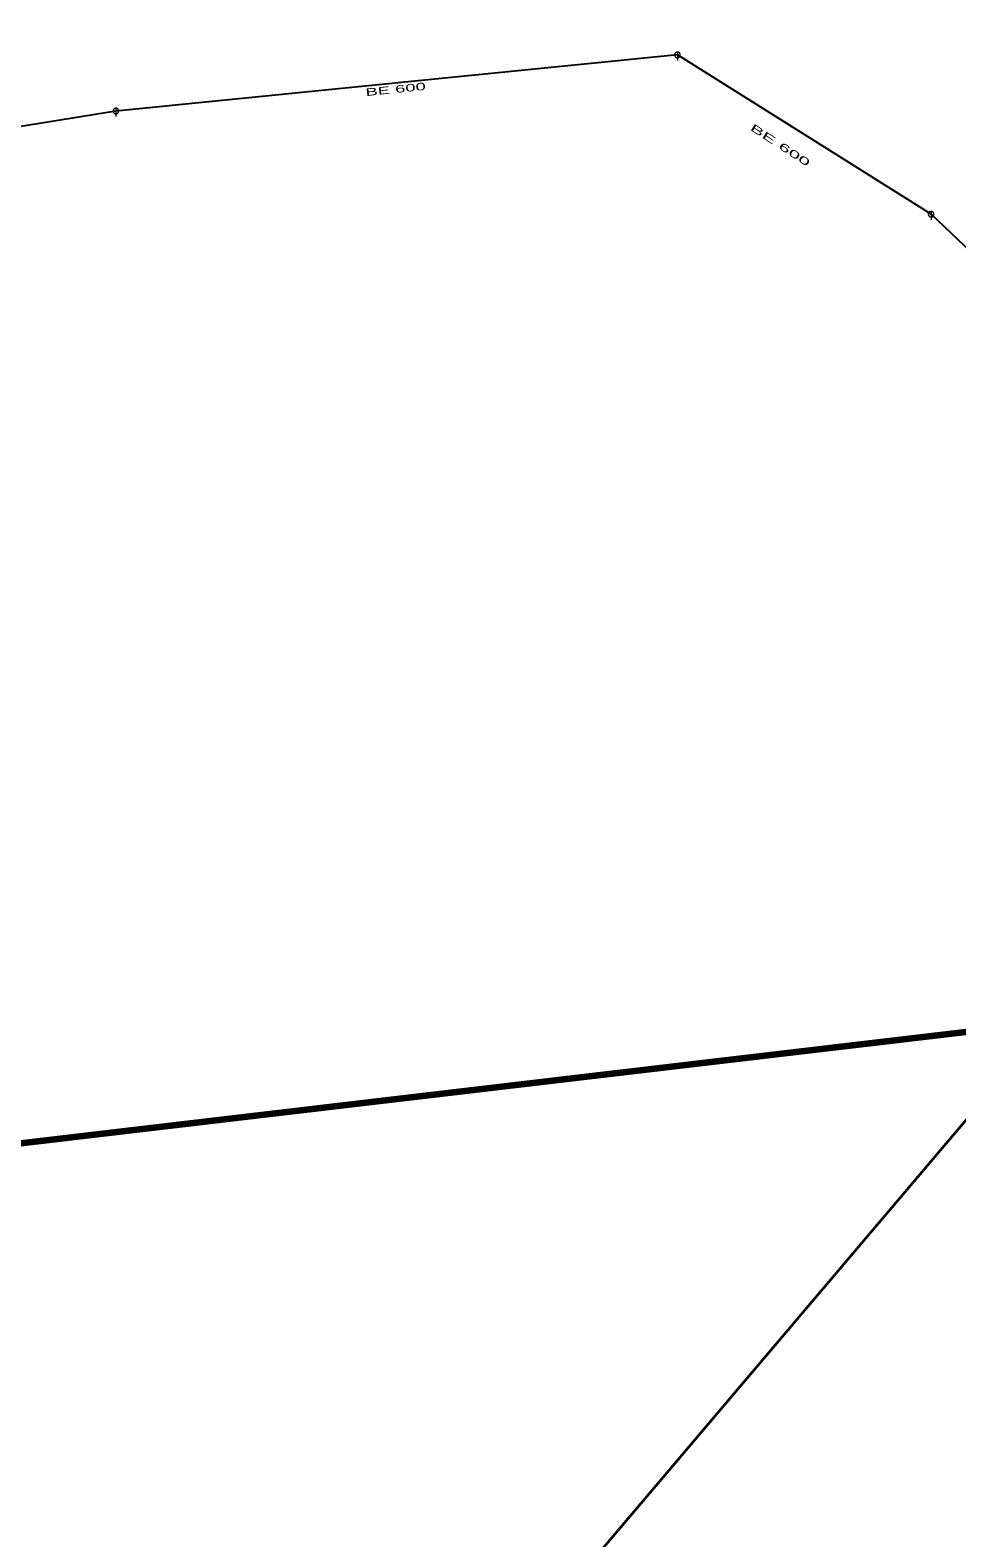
# Model space of a CAD drawing. Extents: x -687468 to -685917, y -974192 to -973456.
# Drawn here: x -686331.6 to -686248.8, y -974006.4 to -973871.6 of the extents above; entities that cross this region are included whole.
import ezdxf
from ezdxf.enums import TextEntityAlignment as Align

# ---------------------------------------------------------------- set-up
doc = ezdxf.new("R2010")
doc.units = 0
doc.header["$LTSCALE"] = 0.27
for name, color, linetype, lineweight in [('1', 7, 'Continuous', 13), ('14', 7, 'Continuous', 25), ('17', 7, 'Continuous', 25), ('22', 7, 'Continuous', 13), ('27', 7, 'Continuous', 158)]:
    doc.layers.add(name, color=color, linetype=linetype, lineweight=lineweight)

msp = doc.modelspace()

# ---------------------------------------------------------------- linework, layer by layer
at = {"layer": '14'}
for p, q in [((-686273.734, -973873.852), (-686323.946, -973878.859)), ((-686251.059, -973888.086), (-686273.734, -973873.852)), ((-686323.946, -973878.859), (-686374.016, -973887.013)), ((-686232.891, -973905.396), (-686251.059, -973888.086)), ((-686200.654, -973955.608), (-686609.228, -974003.734))]:
    msp.add_line(p, q, dxfattribs=at)
at = {"layer": '17', "lineweight": 35}
msp.add_lwpolyline([(-686160.425, -973551.891), (-686169.469, -973574.282), (-686122.999, -973646.384), (-686098.932, -973712.353), (-686089.329, -973782.048), (-686297.791, -974027.806), (-686326.807, -974076.614), (-686379.703, -974100.561), (-686411.584, -974111.413)], dxfattribs=at)
at = {"layer": '22'}
for p, q in [((-686273.733, -973873.6), (-686273.734, -973874.343)), ((-686323.945, -973878.607), (-686323.946, -973879.351)), ((-686251.058, -973887.834), (-686251.059, -973888.578))]:
    msp.add_line(p, q, dxfattribs=at)
for points in [[(-686273.482, -973873.852), (-686273.483, -973873.826), (-686273.487, -973873.8), (-686273.493, -973873.774), (-686273.503, -973873.75), (-686273.515, -973873.726), (-686273.529, -973873.704), (-686273.546, -973873.683), (-686273.564, -973873.665), (-686273.585, -973873.648), (-686273.607, -973873.634), (-686273.631, -973873.622), (-686273.655, -973873.612), (-686273.681, -973873.606), (-686273.707, -973873.602), (-686273.733, -973873.6), (-686273.759, -973873.601), (-686273.785, -973873.605), (-686273.811, -973873.611), (-686273.836, -973873.621), (-686273.859, -973873.633), (-686273.881, -973873.647), (-686273.902, -973873.664), (-686273.92, -973873.682), (-686273.937, -973873.703), (-686273.951, -973873.725), (-686273.963, -973873.749), (-686273.973, -973873.773), (-686273.98, -973873.799), (-686273.984, -973873.825), (-686273.986, -973873.851), (-686273.985, -973873.877), (-686273.981, -973873.903), (-686273.974, -973873.929), (-686273.964, -973873.954), (-686273.952, -973873.977), (-686273.938, -973873.999), (-686273.921, -973874.02), (-686273.903, -973874.038), (-686273.882, -973874.055), (-686273.86, -973874.069), (-686273.837, -973874.081), (-686273.812, -973874.091), (-686273.786, -973874.098), (-686273.76, -973874.102), (-686273.734, -973874.103), (-686273.708, -973874.103), (-686273.682, -973874.099), (-686273.656, -973874.092), (-686273.632, -973874.082), (-686273.608, -973874.07), (-686273.586, -973874.056), (-686273.565, -973874.039), (-686273.547, -973874.021), (-686273.53, -973874), (-686273.516, -973873.978), (-686273.504, -973873.955), (-686273.494, -973873.93), (-686273.488, -973873.904), (-686273.484, -973873.878)], [(-686323.694, -973878.859), (-686323.695, -973878.833), (-686323.699, -973878.807), (-686323.705, -973878.781), (-686323.715, -973878.757), (-686323.727, -973878.733), (-686323.741, -973878.711), (-686323.758, -973878.69), (-686323.776, -973878.672), (-686323.797, -973878.655), (-686323.819, -973878.641), (-686323.843, -973878.629), (-686323.867, -973878.619), (-686323.893, -973878.613), (-686323.919, -973878.609), (-686323.945, -973878.607), (-686323.971, -973878.608), (-686323.997, -973878.612), (-686324.023, -973878.618), (-686324.048, -973878.628), (-686324.071, -973878.64), (-686324.093, -973878.654), (-686324.114, -973878.671), (-686324.132, -973878.689), (-686324.149, -973878.71), (-686324.163, -973878.732), (-686324.175, -973878.756), (-686324.185, -973878.78), (-686324.192, -973878.806), (-686324.196, -973878.832), (-686324.198, -973878.858), (-686324.197, -973878.884), (-686324.193, -973878.91), (-686324.186, -973878.936), (-686324.176, -973878.961), (-686324.164, -973878.984), (-686324.15, -973879.006), (-686324.133, -973879.027), (-686324.115, -973879.045), (-686324.094, -973879.062), (-686324.072, -973879.076), (-686324.049, -973879.088), (-686324.024, -973879.098), (-686323.998, -973879.105), (-686323.972, -973879.109), (-686323.946, -973879.111), (-686323.92, -973879.11), (-686323.894, -973879.106), (-686323.868, -973879.099), (-686323.844, -973879.089), (-686323.82, -973879.077), (-686323.798, -973879.063), (-686323.777, -973879.046), (-686323.759, -973879.028), (-686323.742, -973879.007), (-686323.728, -973878.985), (-686323.716, -973878.962), (-686323.706, -973878.937), (-686323.7, -973878.911), (-686323.696, -973878.885)], [(-686250.807, -973888.086), (-686250.808, -973888.06), (-686250.812, -973888.034), (-686250.818, -973888.008), (-686250.828, -973887.984), (-686250.84, -973887.96), (-686250.854, -973887.938), (-686250.871, -973887.917), (-686250.889, -973887.899), (-686250.91, -973887.882), (-686250.932, -973887.868), (-686250.956, -973887.856), (-686250.98, -973887.846), (-686251.006, -973887.84), (-686251.032, -973887.836), (-686251.058, -973887.834), (-686251.084, -973887.835), (-686251.11, -973887.839), (-686251.136, -973887.845), (-686251.161, -973887.855), (-686251.184, -973887.867), (-686251.206, -973887.881), (-686251.227, -973887.898), (-686251.245, -973887.916), (-686251.262, -973887.937), (-686251.276, -973887.959), (-686251.288, -973887.983), (-686251.298, -973888.007), (-686251.305, -973888.033), (-686251.309, -973888.059), (-686251.311, -973888.085), (-686251.31, -973888.111), (-686251.306, -973888.137), (-686251.299, -973888.163), (-686251.289, -973888.188), (-686251.277, -973888.211), (-686251.263, -973888.233), (-686251.246, -973888.254), (-686251.228, -973888.272), (-686251.207, -973888.289), (-686251.185, -973888.303), (-686251.162, -973888.315), (-686251.137, -973888.325), (-686251.111, -973888.332), (-686251.085, -973888.336), (-686251.059, -973888.338), (-686251.033, -973888.337), (-686251.007, -973888.333), (-686250.981, -973888.326), (-686250.957, -973888.316), (-686250.933, -973888.304), (-686250.911, -973888.29), (-686250.89, -973888.273), (-686250.872, -973888.255), (-686250.855, -973888.234), (-686250.841, -973888.212), (-686250.829, -973888.189), (-686250.819, -973888.164), (-686250.813, -973888.138), (-686250.809, -973888.112)]]:
    msp.add_lwpolyline(points, close=True, dxfattribs=at)
at = {"layer": '27'}
msp.add_lwpolyline([(-686200.654, -973955.608), (-686609.228, -974003.734), (-687014.163, -974137.428)], dxfattribs=at)
msp.add_lwpolyline([(-686200.654, -973955.608), (-686609.228, -974003.734), (-687014.163, -974137.428)], dxfattribs=at)

# ---------------------------------------------------------------- texts
at = {"layer": '1'}
for rotation, width, p in [(6, 1.85, (-686298.903, -973877.245)), (327, 2.1, (-686264.725, -973882.185))]:
    msp.add_text('BE 600', height=0.6667, rotation=rotation, dxfattribs=dict(at, width=width)).set_placement(p, align=Align.CENTER)

doc.saveas('drawing.dxf')
